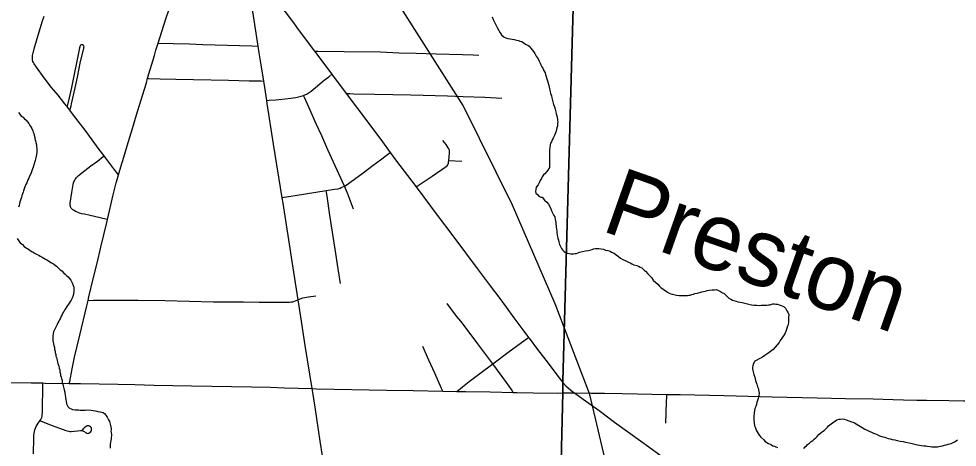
# Model space of a CAD drawing. Extents: x 0 to 34, y 0 to 22.
# Drawn here: x 28.063 to 29.379, y 17.299 to 17.9 of the extents above; entities that cross this region are included whole.
import ezdxf

# ---------------------------------------------------------------- set-up
doc = ezdxf.new("R2010")
doc.units = 0
for name, color, linetype in [('GM_X_City_Street', 7, 'Continuous'), ('GM_X_County_Road', 7, 'Continuous'), ('GM_X_Minor_River', 7, 'Continuous'), ('GM_X_Minor_River_Text', 7, 'Continuous'), ('GM_X_Rail_Line', 7, 'Continuous'), ('GM_X_State_Route', 7, 'Continuous'), ('GM_X_Township_Road', 7, 'Continuous')]:
    doc.layers.add(name, color=color, linetype=linetype)

msp = doc.modelspace()

# ---------------------------------------------------------------- linework, layer by layer
at = {"layer": 'GM_X_City_Street'}
msp.add_line((28.6661, 17.7009), (28.6842, 17.6996), dxfattribs=at)
for points in [[(28.2584, 17.8655), (28.2636, 17.8819), (28.2695, 17.9008), (28.2792, 17.929), (28.2918, 17.9661), (28.2949, 17.9755), (28.2967, 17.9803), (28.2988, 17.9854), (28.301, 17.9905), (28.3029, 17.9946), (28.3046, 17.998), (28.3069, 18.0023), (28.323, 18.0295), (28.34, 18.0581)], [(28.2027, 17.6804), (28.2012, 17.6823), (28.1962, 17.6889), (28.185, 17.7038), (28.1824, 17.7072), (28.1757, 17.7162), (28.1558, 17.7432), (28.1397, 17.7644), (28.1343, 17.7714), (28.1305, 17.7764), (28.1299, 17.7772), (28.1276, 17.7801), (28.118, 17.7922), (28.1089, 17.8032), (28.0982, 17.8169), (28.0875, 17.8315), (28.0844, 17.8362), (28.0833, 17.838), (28.0827, 17.8397), (28.082, 17.8417), (28.0819, 17.8443), (28.0822, 17.8479), (28.0829, 17.8516), (28.0839, 17.855), (28.085, 17.8592), (28.0866, 17.8651), (28.0885, 17.8717), (28.0963, 17.8967), (28.0982, 17.9034)], [(28.1343, 17.7714), (28.1348, 17.7727), (28.1353, 17.7743), (28.1362, 17.7776), (28.1369, 17.7803), (28.1417, 17.8026), (28.145, 17.8177), (28.149, 17.8371), (28.1536, 17.8565), (28.1539, 17.8575), (28.154, 17.8583), (28.1542, 17.8595), (28.1543, 17.8602), (28.1542, 17.861), (28.1539, 17.8619), (28.1533, 17.8625), (28.1528, 17.8628), (28.1513, 17.8632), (28.1504, 17.8632), (28.1493, 17.8626), (28.1487, 17.8618), (28.1481, 17.8586), (28.1367, 17.803), (28.1335, 17.7884), (28.1306, 17.7771), (28.1305, 17.7764)], [(28.2436, 17.816), (28.2513, 17.842), (28.253, 17.848), (28.2553, 17.8557), (28.2584, 17.8655)], [(28.2584, 17.8655), (28.2595, 17.8655), (28.2792, 17.8647), (28.3021, 17.8642), (28.3208, 17.8636), (28.39, 17.8615), (28.3982, 17.8613)], [(28.4776, 17.8542), (28.4825, 17.8541), (28.5193, 17.8537), (28.5701, 17.853), (28.5962, 17.8519), (28.6204, 17.8513), (28.6482, 17.8502), (28.6852, 17.8493), (28.7002, 17.8489), (28.7082, 17.8486)], [(28.2027, 17.6804), (28.2037, 17.6839), (28.2062, 17.692), (28.2102, 17.7053), (28.2149, 17.7214), (28.2223, 17.7458), (28.2281, 17.7648), (28.2341, 17.7844), (28.2418, 17.8099), (28.2436, 17.816)], [(28.2436, 17.816), (28.2448, 17.8159), (28.2612, 17.8153), (28.2832, 17.8148), (28.3078, 17.8143), (28.3568, 17.8132), (28.386, 17.8126), (28.4028, 17.8123), (28.4061, 17.8122)], [(28.4102, 17.7849), (28.414, 17.7852), (28.4235, 17.7859), (28.4407, 17.7876), (28.4517, 17.7892), (28.4591, 17.7908), (28.4624, 17.7919), (28.4672, 17.7943), (28.473, 17.7981), (28.4793, 17.8033), (28.4913, 17.8132), (28.4976, 17.8181), (28.5019, 17.8216)], [(28.5326, 17.6323), (28.5238, 17.655), (28.5197, 17.6649), (28.512, 17.682), (28.5044, 17.6984), (28.4966, 17.7156), (28.4878, 17.7352), (28.4801, 17.752), (28.4696, 17.7756), (28.4638, 17.7889), (28.4624, 17.7919)], [(28.5223, 17.7945), (28.5272, 17.7945), (28.5327, 17.7944), (28.5625, 17.794), (28.6127, 17.7928), (28.6644, 17.7915), (28.6862, 17.7906), (28.7169, 17.7894), (28.7407, 17.7883)], [(28.6661, 17.7009), (28.6667, 17.7059), (28.6673, 17.7115), (28.6673, 17.713), (28.667, 17.7148), (28.6664, 17.7164), (28.6654, 17.7184), (28.6622, 17.723), (28.6578, 17.729)], [(28.4318, 17.6486), (28.4352, 17.6492), (28.4505, 17.6517), (28.4941, 17.6585), (28.5057, 17.6603), (28.5109, 17.6612), (28.5135, 17.662), (28.5153, 17.6627), (28.5197, 17.6649), (28.5233, 17.667), (28.5292, 17.6711), (28.5336, 17.6744), (28.5458, 17.6835), (28.5602, 17.6942), (28.5703, 17.7017), (28.5781, 17.7078), (28.5837, 17.7121)], [(28.1873, 17.6181), (28.1851, 17.6186), (28.1629, 17.6238), (28.155, 17.6254), (28.1514, 17.6261), (28.148, 17.627), (28.1461, 17.6277), (28.1438, 17.6286), (28.1422, 17.6294), (28.1404, 17.6305), (28.1388, 17.6315), (28.1378, 17.6324), (28.1371, 17.6331), (28.1365, 17.6339), (28.1359, 17.6349), (28.1355, 17.6359), (28.1353, 17.6369), (28.1351, 17.6379), (28.135, 17.6395), (28.1351, 17.6412), (28.1355, 17.6437), (28.1359, 17.6469), (28.1374, 17.656), (28.1391, 17.667), (28.1397, 17.6695), (28.1402, 17.6709), (28.1408, 17.672), (28.1414, 17.6733), (28.1421, 17.6745), (28.143, 17.6756), (28.144, 17.6768), (28.1452, 17.6782), (28.1462, 17.6794), (28.1485, 17.6813), (28.1512, 17.6835), (28.164, 17.6932), (28.1731, 17.6999), (28.1813, 17.7063), (28.1824, 17.7072)], [(28.6202, 17.6636), (28.6429, 17.6787), (28.6623, 17.6921), (28.6637, 17.6934), (28.6647, 17.6948), (28.6655, 17.6968), (28.6658, 17.6986), (28.6661, 17.7009)], [(28.1873, 17.6181), (28.1954, 17.6526), (28.1996, 17.6696), (28.2013, 17.6756), (28.2027, 17.6804)], [(28.5141, 17.5281), (28.511, 17.5487), (28.5067, 17.5764), (28.5031, 17.6001), (28.4994, 17.6242), (28.4954, 17.6506), (28.4941, 17.6585)], [(28.16, 17.5045), (28.1612, 17.5094), (28.1672, 17.5348), (28.1726, 17.5565), (28.1781, 17.5794), (28.1863, 17.6139), (28.1873, 17.6181)], [(28.1337, 17.3881), (28.1342, 17.3907), (28.1376, 17.4085), (28.1412, 17.4249), (28.1483, 17.4558), (28.1582, 17.4968), (28.16, 17.5045)], [(28.16, 17.5045), (28.1674, 17.5046), (28.1866, 17.5049), (28.2078, 17.5049), (28.2301, 17.5046), (28.2675, 17.5042), (28.3359, 17.5027), (28.3782, 17.5023), (28.4, 17.5022), (28.4426, 17.5022), (28.4449, 17.5024), (28.4473, 17.5027), (28.4487, 17.5029), (28.4498, 17.5033), (28.452, 17.5042), (28.4543, 17.5053), (28.4574, 17.5068), (28.4588, 17.5074), (28.46, 17.5078), (28.4613, 17.5082), (28.4695, 17.5093), (28.4797, 17.511)], [(28.7564, 17.3755), (28.7539, 17.3793), (28.7506, 17.3842), (28.7434, 17.3943), (28.7277, 17.4156), (28.7069, 17.4437), (28.6945, 17.4599), (28.6828, 17.4752), (28.6771, 17.4825), (28.6636, 17.5002)], [(28.6774, 17.3768), (28.6855, 17.3834), (28.6946, 17.3909), (28.7095, 17.4022), (28.7277, 17.4156), (28.7489, 17.4316), (28.7731, 17.4492), (28.778, 17.4527)], [(28.6577, 17.3772), (28.6561, 17.3807), (28.6464, 17.4024), (28.6381, 17.4208), (28.6295, 17.4399)], [(28.0833, 17.2895), (28.0838, 17.3116), (28.0841, 17.3148), (28.0845, 17.3185), (28.0849, 17.3207), (28.0855, 17.3229), (28.0863, 17.3252), (28.0874, 17.3276), (28.0884, 17.3298), (28.0898, 17.3321), (28.0926, 17.3359), (28.0938, 17.3376), (28.095, 17.3402), (28.0955, 17.3421), (28.0958, 17.3443), (28.0961, 17.3464), (28.0963, 17.3491), (28.0967, 17.3864), (28.0967, 17.3887)], [(28.9705, 17.3321), (28.971, 17.3467), (28.9715, 17.3623), (28.9718, 17.3694), (28.9719, 17.3727)], [(28.0926, 17.3359), (28.094, 17.3353), (28.1096, 17.3292), (28.1199, 17.3253), (28.1288, 17.3219), (28.1307, 17.3214), (28.1328, 17.321), (28.1346, 17.3207), (28.1364, 17.3208), (28.1494, 17.3221), (28.1515, 17.3219), (28.1535, 17.3211), (28.1567, 17.319), (28.1576, 17.3185), (28.1585, 17.3181), (28.1595, 17.318), (28.1606, 17.3181), (28.1617, 17.3185), (28.1626, 17.319), (28.1634, 17.3197), (28.1643, 17.321), (28.1646, 17.3218), (28.1648, 17.3231), (28.1648, 17.3247), (28.1646, 17.3256), (28.1642, 17.3263), (28.1634, 17.3273), (28.162, 17.3281), (28.1609, 17.3284), (28.1598, 17.3285), (28.1585, 17.3284), (28.1574, 17.3278), (28.156, 17.3269), (28.1552, 17.3261), (28.1543, 17.3252), (28.1533, 17.3242), (28.1517, 17.3224)]]:
    msp.add_lwpolyline(points, dxfattribs=at)
at = {"layer": 'GM_X_County_Road'}
for p, q in [((28.4776, 17.8542), (28.5019, 17.8216)), ((28.6577, 17.3772), (28.6774, 17.3768))]:
    msp.add_line(p, q, dxfattribs=at)
for points in [[(28.4304, 17.917), (28.4322, 17.9146), (28.4382, 17.9067), (28.4491, 17.8924), (28.455, 17.8845), (28.4624, 17.8747), (28.466, 17.8697), (28.4776, 17.8542)], [(28.5019, 17.8216), (28.5028, 17.8204), (28.5223, 17.7945)], [(28.5223, 17.7945), (28.5525, 17.7543), (28.5729, 17.7269), (28.5837, 17.7121)], [(28.5837, 17.7121), (28.5928, 17.6999), (28.6082, 17.6797), (28.6202, 17.6636)], [(28.6202, 17.6636), (28.6309, 17.6492), (28.6499, 17.6239), (28.6717, 17.5952), (28.706, 17.5494), (28.7241, 17.5249), (28.7375, 17.507), (28.7464, 17.495), (28.7575, 17.48), (28.7701, 17.4631), (28.778, 17.4527)], [(28.778, 17.4527), (28.7788, 17.4517), (28.7907, 17.4358), (28.8055, 17.4166), (28.8192, 17.3981), (28.8263, 17.3895), (28.8304, 17.3849), (28.834, 17.3816), (28.8401, 17.3764), (28.8425, 17.3747)], [(28.0176, 17.3901), (28.0353, 17.3898), (28.0502, 17.3894), (28.08, 17.389), (28.0967, 17.3887)], [(28.0967, 17.3887), (28.0999, 17.3886), (28.1337, 17.3881)], [(28.1337, 17.3881), (28.1496, 17.3878), (28.2018, 17.3868), (28.2254, 17.3864), (28.2528, 17.3858), (28.305, 17.3849), (28.3895, 17.3834), (28.4156, 17.3827), (28.4356, 17.382), (28.4739, 17.3807)], [(28.4739, 17.3807), (28.4804, 17.3806), (28.5793, 17.3787), (28.616, 17.378), (28.6577, 17.3772)], [(28.6774, 17.3768), (28.6894, 17.3765), (28.7242, 17.3762), (28.7564, 17.3755)], [(28.7564, 17.3755), (28.7616, 17.3753), (28.7846, 17.3749), (28.8181, 17.3746), (28.8263, 17.3747), (28.8341, 17.3747), (28.8425, 17.3747)], [(28.8425, 17.3747), (28.8546, 17.3658), (28.8769, 17.3499), (28.8988, 17.3335), (28.9201, 17.3184), (28.9353, 17.3076), (28.9467, 17.299), (28.9587, 17.2902), (28.994, 17.2648), (29.0009, 17.2598)], [(28.8425, 17.3747), (28.8665, 17.3746), (28.8845, 17.3745), (28.9093, 17.374), (28.9719, 17.3727)], [(28.9719, 17.3727), (28.9814, 17.3725), (28.9862, 17.3724)], [(28.9862, 17.3724), (28.9906, 17.3723), (29.0526, 17.371), (29.1198, 17.3694), (29.183, 17.3679), (29.2227, 17.367), (29.2614, 17.3664)], [(29.2614, 17.3664), (29.2894, 17.3655), (29.3043, 17.3651), (29.3229, 17.3648), (29.3362, 17.3646), (29.3679, 17.3641), (29.3883, 17.3637), (29.4168, 17.3634), (29.4405, 17.363), (29.4649, 17.3621), (29.502, 17.3612), (29.5635, 17.3593), (29.6487, 17.3575), (29.696, 17.3563), (29.7498, 17.355), (29.7636, 17.3547)]]:
    msp.add_lwpolyline(points, dxfattribs=at)
at = {"layer": 'GM_X_Minor_River'}
for points in [[(28.7271, 17.9021), (28.7285, 17.8983), (28.7303, 17.8948), (28.7321, 17.891), (28.7339, 17.8875), (28.7382, 17.8798), (28.74, 17.8771), (28.7437, 17.8739), (28.7463, 17.8727), (28.749, 17.8719), (28.7524, 17.8714), (28.755, 17.8709), (28.7577, 17.8705), (28.7611, 17.8696), (28.7637, 17.8692), (28.7656, 17.8683), (28.7686, 17.8675), (28.7723, 17.8647), (28.7746, 17.8635), (28.7768, 17.8623), (28.7787, 17.8611), (28.7813, 17.8584), (28.7831, 17.856), (28.7849, 17.8537), (28.7867, 17.8506), (28.7889, 17.8471), (28.7915, 17.8433), (28.7929, 17.8402), (28.7943, 17.8371), (28.7954, 17.8348), (28.7968, 17.8321), (28.7979, 17.8301), (28.7986, 17.8282), (28.8001, 17.8259), (28.8011, 17.8236), (28.8018, 17.8213), (28.8025, 17.8186), (28.8036, 17.8152), (28.8046, 17.8125), (28.8057, 17.8094), (28.8063, 17.8059), (28.8073, 17.8014), (28.8084, 17.7975), (28.809, 17.7948), (28.8101, 17.7914), (28.8108, 17.7887), (28.8132, 17.7795), (28.8142, 17.7761), (28.8152, 17.7726), (28.8163, 17.7692), (28.8169, 17.7661), (28.8176, 17.7634), (28.8183, 17.7611), (28.8186, 17.7588), (28.8186, 17.7569), (28.8189, 17.755), (28.8185, 17.7527), (28.8184, 17.7493), (28.8175, 17.7467), (28.8171, 17.7444), (28.8166, 17.7418), (28.8158, 17.7395), (28.815, 17.7373), (28.8138, 17.735), (28.8125, 17.732), (28.8113, 17.7298), (28.8101, 17.7271), (28.8089, 17.7249), (28.8085, 17.7226), (28.808, 17.7188), (28.8075, 17.715), (28.8074, 17.7112), (28.8073, 17.7082), (28.8076, 17.7055), (28.8075, 17.7025), (28.8074, 17.6987), (28.8073, 17.696), (28.8073, 17.6941), (28.8072, 17.6907), (28.8051, 17.687), (28.8032, 17.6848), (28.8008, 17.6822), (28.7989, 17.6807), (28.7973, 17.6777), (28.7961, 17.6754), (28.7945, 17.6728), (28.7929, 17.6695), (28.7913, 17.6668), (28.7889, 17.6635)], [(28.0626, 17.768), (28.0645, 17.7657), (28.0663, 17.763), (28.0689, 17.7614), (28.0704, 17.7595), (28.073, 17.7571), (28.0752, 17.7548), (28.077, 17.7528), (28.0784, 17.7497), (28.0795, 17.7478), (28.081, 17.7455), (28.0824, 17.7424), (28.0831, 17.7405), (28.0838, 17.7385), (28.0845, 17.7362), (28.0852, 17.7332), (28.0855, 17.7313), (28.0862, 17.7282), (28.0869, 17.7259), (28.0875, 17.7228), (28.0878, 17.7198), (28.0881, 17.7175), (28.0881, 17.7148), (28.088, 17.7126), (28.0875, 17.7092), (28.0871, 17.7069), (28.0862, 17.7027), (28.0858, 17.7005), (28.0828, 17.6914), (28.082, 17.6892), (28.0812, 17.6861), (28.0799, 17.682), (28.0779, 17.6786), (28.0767, 17.676), (28.0755, 17.6734), (28.0742, 17.6696), (28.0726, 17.667), (28.0718, 17.6651), (28.071, 17.6625), (28.0701, 17.6598), (28.0693, 17.658), (28.0689, 17.6561), (28.0681, 17.6542), (28.0672, 17.6516), (28.0664, 17.6489), (28.0656, 17.6463), (28.0647, 17.6436), (28.0639, 17.6403), (28.0634, 17.6376), (28.0626, 17.6353)], [(28.7889, 17.6635), (28.788, 17.6601), (28.7876, 17.6571), (28.7883, 17.6551), (28.7909, 17.6524), (28.7923, 17.6505), (28.7953, 17.6492), (28.7972, 17.6492), (28.8005, 17.6449), (28.8035, 17.6425), (28.8061, 17.6394), (28.8079, 17.6363), (28.8093, 17.6329), (28.8107, 17.6294), (28.8125, 17.6255), (28.8136, 17.6236), (28.8147, 17.6217), (28.8153, 17.6182), (28.816, 17.6159), (28.8163, 17.614), (28.8162, 17.6114), (28.8169, 17.6091), (28.8169, 17.6072), (28.8172, 17.6045), (28.8175, 17.6014), (28.8178, 17.5992), (28.8181, 17.5965), (28.8188, 17.5938), (28.8191, 17.5919), (28.8198, 17.5888), (28.8205, 17.5865), (28.8215, 17.5827), (28.8229, 17.58), (28.8244, 17.5773), (28.8255, 17.5754), (28.8273, 17.5734), (28.8303, 17.571), (28.8371, 17.5697), (28.8409, 17.57), (28.8432, 17.5703), (28.8451, 17.5702), (28.8497, 17.572), (28.8539, 17.573), (28.8577, 17.5741), (28.8615, 17.5747), (28.8653, 17.5754), (28.8673, 17.5757), (28.8692, 17.5768), (28.8719, 17.5771), (28.8741, 17.5774), (28.8768, 17.5773), (28.8798, 17.5768), (28.8832, 17.5764), (28.8862, 17.5751), (28.8892, 17.5743), (28.8923, 17.5734), (28.8945, 17.5722), (28.8979, 17.5706), (28.9009, 17.5686), (28.9042, 17.5663), (28.9072, 17.5639), (28.9105, 17.5619), (28.9135, 17.5603), (28.9162, 17.5591), (28.9184, 17.5579), (28.9206, 17.557), (28.9229, 17.5558), (28.9255, 17.5546), (28.9297, 17.5534), (28.9323, 17.5525), (28.9345, 17.5513), (28.9368, 17.5501), (28.9386, 17.5485), (28.9405, 17.5466), (28.9423, 17.5454), (28.9453, 17.5419), (28.9479, 17.5395), (28.9504, 17.5368), (28.953, 17.5329), (28.9567, 17.5298), (28.9593, 17.5274), (28.9615, 17.5251), (28.9637, 17.5227), (28.973, 17.516), (28.9764, 17.5144), (28.9794, 17.5131), (28.9817, 17.5127), (28.9854, 17.5118), (28.9892, 17.5113), (28.9919, 17.5113), (28.9945, 17.5116), (28.9976, 17.5115), (29.001, 17.5114), (29.0029, 17.5117), (29.0048, 17.512), (29.0071, 17.5127), (29.0094, 17.5134), (29.0113, 17.5141), (29.0151, 17.5148), (29.0209, 17.5165), (29.0236, 17.5172)], [(28.0606, 17.5913), (28.0635, 17.587), (28.0649, 17.5851), (28.0679, 17.5827), (28.0705, 17.58), (28.0724, 17.5788), (28.0742, 17.5776)], [(28.0742, 17.5776), (28.0776, 17.5752), (28.0805, 17.5732), (28.0824, 17.5724), (28.0847, 17.5708), (28.0884, 17.5688), (28.0907, 17.568), (28.0929, 17.5664), (28.0955, 17.5652), (28.0981, 17.5636), (28.1004, 17.5624), (28.1022, 17.5612), (28.1045, 17.56), (28.1063, 17.5588), (28.1086, 17.5572), (28.1116, 17.5556), (28.1138, 17.554), (28.1156, 17.5524), (28.119, 17.5493), (28.1208, 17.5474), (28.1231, 17.5458), (28.126, 17.5426), (28.1279, 17.5411), (28.1297, 17.5395), (28.1319, 17.5375), (28.1341, 17.5352), (28.136, 17.5329), (28.1367, 17.5309), (28.1378, 17.529), (28.1392, 17.5255), (28.1399, 17.5229), (28.1402, 17.5209), (28.1401, 17.519), (28.1401, 17.5164), (28.1392, 17.5115), (28.1379, 17.5077), (28.1363, 17.5047), (28.1351, 17.5028), (28.1335, 17.5006), (28.1315, 17.4976), (28.1303, 17.4958), (28.128, 17.4924), (28.126, 17.489), (28.1248, 17.4872), (28.1236, 17.4845), (28.1223, 17.4823), (28.1211, 17.4797), (28.1199, 17.4774), (28.1191, 17.4752), (28.1175, 17.4729), (28.1167, 17.4707), (28.1155, 17.4688), (28.1147, 17.4669), (28.1139, 17.465), (28.1127, 17.4632), (28.1115, 17.4606), (28.111, 17.4575), (28.1105, 17.4545), (28.1105, 17.4522), (28.1104, 17.4503), (28.1107, 17.4484), (28.111, 17.4461), (28.1117, 17.4438), (28.112, 17.4411), (28.1127, 17.4385), (28.113, 17.4358), (28.1137, 17.4335), (28.114, 17.4312), (28.1147, 17.4285), (28.115, 17.4262), (28.1157, 17.4243), (28.1161, 17.4224), (28.1178, 17.4159), (28.1188, 17.4124), (28.1195, 17.4094), (28.1202, 17.4071), (28.1205, 17.4044), (28.1212, 17.4017), (28.1215, 17.3994), (28.1221, 17.3967), (28.1229, 17.3948), (28.1235, 17.3921), (28.1238, 17.3895), (28.1245, 17.3872), (28.1252, 17.3849), (28.1255, 17.383), (28.1259, 17.381), (28.1266, 17.3791), (28.1272, 17.3757), (28.1276, 17.3738), (28.1279, 17.3719), (28.1285, 17.3684), (28.1288, 17.365), (28.1291, 17.3631), (28.1298, 17.3596), (28.1305, 17.3577), (28.1316, 17.3558), (28.1338, 17.3534), (28.1361, 17.3522), (28.1383, 17.3514), (28.1421, 17.3509)], [(29.0236, 17.5172), (29.0262, 17.5175), (29.0285, 17.5182), (29.0312, 17.5189), (29.0358, 17.5195), (29.0388, 17.5194), (29.0411, 17.5197), (29.0445, 17.5185), (29.0471, 17.5169), (29.0501, 17.5153), (29.052, 17.5145), (29.0549, 17.5117), (29.0568, 17.5098), (29.059, 17.5078), (29.0616, 17.5062), (29.0642, 17.5046), (29.0672, 17.5041), (29.0695, 17.5033), (29.0718, 17.5025), (29.0748, 17.502), (29.0778, 17.5015), (29.0906, 17.4985), (29.094, 17.498), (29.0982, 17.4979), (29.1016, 17.4974), (29.1043, 17.4977), (29.1069, 17.4977), (29.11, 17.498), (29.1119, 17.4979), (29.1146, 17.4982), (29.1165, 17.4985), (29.1207, 17.4996), (29.1229, 17.4995), (29.1248, 17.4994), (29.1271, 17.499), (29.1297, 17.4982), (29.1324, 17.4973), (29.1346, 17.4965), (29.1365, 17.4957), (29.1384, 17.4937), (29.1405, 17.4899), (29.142, 17.4879), (29.143, 17.4845), (29.1429, 17.4803), (29.1428, 17.4776), (29.1427, 17.4742), (29.1422, 17.4704), (29.1414, 17.4682), (29.1406, 17.4655), (29.1393, 17.4625), (29.1381, 17.4587), (29.1357, 17.455), (29.1333, 17.4513), (29.131, 17.4483), (29.1294, 17.4453), (29.127, 17.4423), (29.1242, 17.439), (29.1211, 17.4357), (29.1157, 17.4316), (29.1122, 17.4291), (29.1095, 17.4273), (29.1064, 17.4251), (29.1033, 17.4233), (29.0956, 17.4193), (29.0936, 17.4159), (29.0927, 17.4129), (29.0923, 17.411), (29.0922, 17.4084), (29.0932, 17.4041), (29.0943, 17.4007), (29.0949, 17.398), (29.096, 17.3949), (29.0963, 17.3923), (29.0973, 17.3892), (29.0984, 17.3869), (29.0991, 17.3831), (29.1005, 17.3804), (29.1008, 17.3785), (29.1015, 17.3746), (29.101, 17.3705), (29.1001, 17.3671), (29.0993, 17.3641), (29.0984, 17.3618), (29.0976, 17.3584), (29.0967, 17.3558), (29.0955, 17.3531), (29.0946, 17.3467), (29.0941, 17.3414), (29.0943, 17.3364), (29.0952, 17.3284), (29.0963, 17.3257), (29.0973, 17.3227), (29.0988, 17.32), (29.1002, 17.318), (29.1017, 17.3153), (29.1039, 17.3126), (29.1079, 17.3087), (29.1101, 17.3067), (29.1124, 17.3051), (29.1146, 17.3039), (29.1169, 17.3027)], [(28.1421, 17.3509), (28.1444, 17.3509), (28.1466, 17.3508), (28.1489, 17.3507), (28.1523, 17.3506), (28.1561, 17.3505), (28.1584, 17.3508), (28.1645, 17.3507), (28.1671, 17.3502), (28.1702, 17.3497), (28.1721, 17.3493), (28.1739, 17.3489), (28.177, 17.348), (28.1788, 17.3476), (28.1811, 17.3471), (28.1833, 17.3456), (28.1848, 17.3436), (28.1866, 17.3409), (28.1888, 17.337), (28.1899, 17.3347), (28.1906, 17.3328), (28.1916, 17.329), (28.1919, 17.3271), (28.1922, 17.3248), (28.1922, 17.3229), (28.1921, 17.321), (28.1924, 17.3187), (28.1928, 17.3168), (28.1927, 17.3149), (28.1926, 17.3122), (28.1926, 17.3103), (28.1921, 17.308), (28.1917, 17.3054), (28.1912, 17.3027), (28.1911, 17.3001), (28.1911, 17.2974)], [(29.1642, 17.2968), (29.1661, 17.299), (29.1681, 17.3005), (29.1693, 17.3023), (29.172, 17.3042), (29.1747, 17.3067), (29.1767, 17.3082), (29.1786, 17.3097), (29.1809, 17.3119), (29.1829, 17.3137), (29.1852, 17.3163), (29.188, 17.3189), (29.1903, 17.3207), (29.1926, 17.3222), (29.1954, 17.3248), (29.1973, 17.3266), (29.1989, 17.3285), (29.2008, 17.3299), (29.2043, 17.3329), (29.2063, 17.3343), (29.2086, 17.3358), (29.2105, 17.3369), (29.2136, 17.3379), (29.2155, 17.3379), (29.2189, 17.3382), (29.2212, 17.3377), (29.2238, 17.3369), (29.2276, 17.3356), (29.231, 17.3344), (29.2336, 17.3336), (29.2355, 17.3327), (29.2437, 17.3276), (29.2463, 17.326), (29.2497, 17.324), (29.253, 17.3224), (29.2557, 17.3211), (29.259, 17.3195), (29.262, 17.3183), (29.2647, 17.3175), (29.2673, 17.3166), (29.2703, 17.3146), (29.2752, 17.3133), (29.2778, 17.3125), (29.2801, 17.3117), (29.2827, 17.3108), (29.2854, 17.3104), (29.2884, 17.3095), (29.2918, 17.3087), (29.2952, 17.3082), (29.2993, 17.3069), (29.3035, 17.3064), (29.3069, 17.3056), (29.3122, 17.3047), (29.3163, 17.3038), (29.3201, 17.3029), (29.3235, 17.3021), (29.3265, 17.3016), (29.3295, 17.3011), (29.3325, 17.3007), (29.3352, 17.3006), (29.3378, 17.3001), (29.3409, 17.2997), (29.3439, 17.2992), (29.3466, 17.2991), (29.3496, 17.299), (29.3519, 17.2993), (29.3538, 17.2997), (29.3561, 17.3), (29.3588, 17.3007), (29.3614, 17.3014), (29.3641, 17.302), (29.3668, 17.3027), (29.3691, 17.3034), (29.371, 17.3037), (29.3737, 17.3052), (29.3756, 17.3063), (29.378, 17.3077), (29.3799, 17.3088)], [(29.1169, 17.3027), (29.1187, 17.3019), (29.1206, 17.3007), (29.1229, 17.2999), (29.1251, 17.299), (29.1274, 17.2982)]]:
    msp.add_lwpolyline(points, dxfattribs=at)
at = {"layer": 'GM_X_Rail_Line'}
msp.add_lwpolyline([(29.7358, 14.1), (29.6819, 14.2915), (29.4151, 15.3006), (29.1953, 16.1186), (28.963, 16.952), (28.8642, 17.3725), (28.8153, 17.4999), (28.7556, 17.6382), (28.6863, 17.7778), (28.4883, 18.0894), (28.4584, 18.1342), (28.4272, 18.1626), (28.3947, 18.1748), (28.3594, 18.181)], dxfattribs=at)
at = {"layer": 'GM_X_State_Route'}
for points in [[(28.3805, 17.9758), (28.3839, 17.9535), (28.3916, 17.9035), (28.3982, 17.8613), (28.3997, 17.8519), (28.4028, 17.8323), (28.4061, 17.8122), (28.4076, 17.803), (28.4102, 17.7849), (28.4108, 17.7809), (28.4198, 17.7238), (28.4318, 17.6486), (28.4331, 17.6409), (28.4458, 17.5593), (28.4543, 17.5053), (28.4582, 17.4813), (28.4642, 17.4414), (28.4739, 17.3807)], [(28.4739, 17.3807), (28.4752, 17.3726), (28.478, 17.3548), (28.4853, 17.3069), (28.4885, 17.2866), (28.4945, 17.2486), (28.5021, 17.1983), (28.5059, 17.1736), (28.5062, 17.1717), (28.5063, 17.1707)]]:
    msp.add_lwpolyline(points, dxfattribs=at)
at = {"layer": 'GM_X_Township_Road'}
for points in [[(28.8168, 16.9882), (28.8261, 17.3752), (28.826, 17.3901), (28.8261, 17.3911), (28.8399, 17.8824), (28.8457, 18.0882), (28.8471, 18.1346), (28.8477, 18.1576), (28.8485, 18.1889), (28.8508, 18.2811), (28.851, 18.2882), (28.8514, 18.3143), (28.8519, 18.3416), (28.8522, 18.3576), (28.8529, 18.3862), (28.8621, 18.7381), (28.6128, 18.7956), (28.4415, 18.7977), (28.2231, 18.7757), (27.8611, 18.8638)], [(28.8641, 18.8622), (28.8621, 18.7381), (28.8529, 18.3862), (28.8522, 18.3576), (28.8519, 18.3416), (28.8514, 18.3143), (28.851, 18.2882), (28.8508, 18.2811), (28.8485, 18.1889), (28.8477, 18.1576), (28.8471, 18.1346), (28.8457, 18.0882), (28.8399, 17.8824), (28.8261, 17.3911), (28.826, 17.3901), (28.8261, 17.3752), (28.8168, 16.9882)]]:
    msp.add_lwpolyline(points, dxfattribs=at)

# ---------------------------------------------------------------- texts
at = {"layer": 'GM_X_Minor_River_Text'}
msp.add_text('Preston', height=0.09475, rotation=340.6161, dxfattribs=at).set_placement((28.8779, 17.6031))

doc.saveas('drawing.dxf')
